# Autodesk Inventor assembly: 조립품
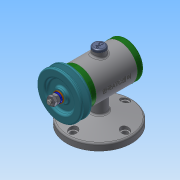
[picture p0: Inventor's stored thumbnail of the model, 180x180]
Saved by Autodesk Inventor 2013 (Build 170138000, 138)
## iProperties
Created: 2018-12
Part Number: 조립품
Document SubType Name: Assembly
Designer: Administrator
Author: Administrator
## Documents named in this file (15)
- C:\Users\Administrator\Desktop\481207V1057\조립품.iam
- C:\Users\Administrator\Desktop\481207V1057\본체.ipt
- C:\Users\Administrator\Desktop\481207V1057\축.ipt
- C:\Users\Administrator\Desktop\481207V1057\키 3 x 3 x 12.ipt
- C:\Users\Administrator\Desktop\481207V1057\베어링 15 x 32 x 9.ipt
- C:\Users\Administrator\Desktop\481207V1057\앞커버.ipt
- C:\Users\Administrator\Desktop\481207V1057\오일 실 15 25 7.ipt
- C:\Users\Administrator\Desktop\481207V1057\볼트 M4 x 12.ipt
- C:\Users\Administrator\Desktop\481207V1057\V벨트풀리.ipt
- C:\Users\Administrator\Desktop\481207V1057\와셔 8x17.ipt
- C:\Users\Administrator\Desktop\481207V1057\너트 M8.ipt
- 너트 M8.ipt
- C:\Users\Administrator\Desktop\481207V1057\뒤커버.ipt
- C:\Users\Administrator\Desktop\481207V1057\고무캡.ipt
- C:\Users\Administrator\Desktop\481207V1057\스프링와셔 8.ipt
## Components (2 placed, 2 different names)
1. V벨트풀리:1
2. 고무캡:1
